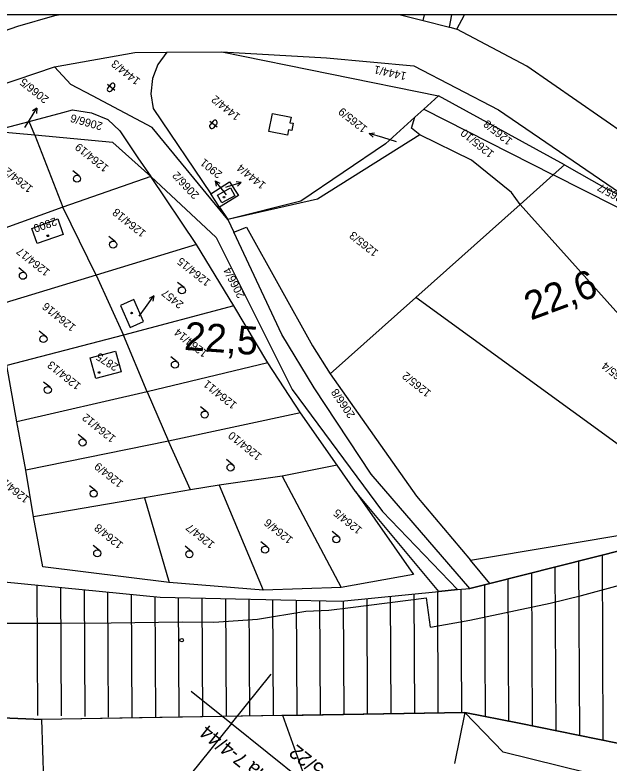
# Model space of a CAD drawing. Extents: x -794765 to -785424, y -1118958 to -1108731.
# Drawn here: x -794200.3 to -794074.2, y -1110190.3 to -1110031.4 of the extents above; entities that cross this region are included whole.
import ezdxf

# ---------------------------------------------------------------- set-up
doc = ezdxf.new("R2010")
doc.units = 0
for name, color, linetype in [('Level 66', 7, 'Continuous'), ('Level 71', 7, 'Continuous'), ('Level 73', 7, 'Continuous'), ('Level 75', 7, 'Continuous'), ('Level 76', 7, 'Continuous'), ('Level 77', 7, 'Continuous'), ('Level 78', 7, 'Continuous'), ('Level 79', 7, 'Continuous'), ('Level 80', 7, 'Continuous'), ('Vrstva 1', 7, 'Continuous'), ('Vrstva 53', 7, 'Continuous')]:
    doc.layers.add(name, color=color, linetype=linetype)

msp = doc.modelspace()

# ---------------------------------------------------------------- linework, layer by layer
at = {"layer": 'Level 66'}
for p, q in [((-794179.12, -1110047.46), (-794180.69, -1110046.2)), ((-794179.98, -1110046.12), (-794180.61, -1110046.91)), ((-794179.83, -1110047.53), (-794179.2, -1110046.75)), ((-794157.42, -1110055.31), (-794158.98, -1110054.06)), ((-794158.27, -1110053.98), (-794158.9, -1110054.76)), ((-794158.12, -1110055.39), (-794157.49, -1110054.61)), ((-794186.69, -1110065.64), (-794188.06, -1110064.55)), ((-794179.01, -1110079.63), (-794180.38, -1110078.53)), ((-794198.17, -1110086.26), (-794199.54, -1110085.17)), ((-794164.42, -1110089.36), (-794165.79, -1110088.27)), ((-794193.8, -1110099.71), (-794195.17, -1110098.61)), ((-794165.9, -1110105.14), (-794167.26, -1110104.04)), ((-794192.88, -1110110.51), (-794194.24, -1110109.42)), ((-794159.57, -1110115.75), (-794160.94, -1110114.65)), ((-794185.51, -1110121.67), (-794186.88, -1110120.58)), ((-794154.09, -1110126.99), (-794155.45, -1110125.89)), ((-794183.15, -1110132.54), (-794184.51, -1110131.44)), ((-794131.62, -1110142.24), (-794132.98, -1110141.14)), ((-794146.75, -1110144.45), (-794148.11, -1110143.35)), ((-794182.39, -1110145.21), (-794183.75, -1110144.12)), ((-794162.83, -1110145.41), (-794164.2, -1110144.31))]:
    msp.add_line(p, q, dxfattribs=at)
for centre in [(-794187.16, -1110066.23), (-794179.48, -1110080.21), (-794198.64, -1110086.85), (-794164.89, -1110089.95), (-794194.27, -1110100.29), (-794166.37, -1110105.72), (-794193.35, -1110111.1), (-794160.04, -1110116.33), (-794185.98, -1110122.26), (-794154.56, -1110127.57), (-794183.62, -1110133.12), (-794132.09, -1110142.82), (-794182.86, -1110145.8), (-794163.3, -1110145.99), (-794147.22, -1110145.03)]:
    msp.add_circle(centre, 0.75, dxfattribs=at)
for centre, start, end in [((-794179.59, -1110046.44), 321.279, 141.2669), ((-794180.22, -1110047.22), 141.279, 321.279), ((-794158.51, -1110055.07), 141.279, 321.279), ((-794157.88, -1110054.29), 321.279, 141.2669)]:
    msp.add_arc(centre, 0.5, start, end, dxfattribs=at)
at = {"layer": 'Level 71'}
msp.add_lwpolyline([(-793908.08, -1110031.45), (-794753.93, -1110031.45), (-794753.93, -1110332.22), (-793908.08, -1110332.22)], dxfattribs=at)
at = {"layer": 'Level 75'}
for p, q in [((-794106.52, -1110034.45), (-794104.92, -1110031.45)), ((-794108.04, -1110034.02), (-794107.69, -1110034.1)), ((-794107.69, -1110034.1), (-794106.52, -1110034.45)), ((-794091.69, -1110042.34), (-794106.52, -1110034.45)), ((-794191.91, -1110042.47), (-794174.87, -1110039.43)), ((-794174.87, -1110039.43), (-794168.06, -1110039.38)), ((-794168.06, -1110039.38), (-794156.44, -1110039.29)), ((-794156.44, -1110039.29), (-794110.41, -1110048.62)), ((-794212.78, -1110049.48), (-794191.91, -1110042.47)), ((-794028.04, -1110086.43), (-794091.69, -1110042.34)), ((-794110.41, -1110048.62), (-794113.55, -1110051.47)), ((-794083.67, -1110063.3), (-794110.41, -1110048.62)), ((-794113.55, -1110051.47), (-794115.45, -1110053.18)), ((-794113.55, -1110051.47), (-794086.03, -1110065.42)), ((-794097.7, -1110051.61), (-794069.06, -1110071.16)), ((-794205.18, -1110056.17), (-794197.29, -1110054.06)), ((-794196.14, -1110057), (-794197.29, -1110054.06)), ((-794196.14, -1110057), (-794205.18, -1110056.17)), ((-794196.14, -1110057), (-794190.13, -1110072.26)), ((-794086.03, -1110065.42), (-794083.67, -1110063.3)), ((-794171.51, -1110065.77), (-794190.13, -1110072.26)), ((-794161.77, -1110080.2), (-794171.51, -1110065.77)), ((-794093.09, -1110071.73), (-794086.03, -1110065.42)), ((-794156.87, -1110072.29), (-794158.77, -1110069.45)), ((-794190.13, -1110072.26), (-794207.61, -1110078.55)), ((-794183.1, -1110086.74), (-794190.13, -1110072.26)), ((-794156.87, -1110072.29), (-794155.11, -1110074.89)), ((-794115.2, -1110091.49), (-794093.09, -1110071.73)), ((-794155.11, -1110074.89), (-794153.84, -1110077.58)), ((-794161.77, -1110080.2), (-794183.1, -1110086.74)), ((-794153.84, -1110093.26), (-794161.77, -1110080.2)), ((-794183.1, -1110086.74), (-794204.4, -1110093.2)), ((-794183.1, -1110086.74), (-794177.29, -1110099.49)), ((-794115.2, -1110091.49), (-794133.43, -1110107.64)), ((-794057.76, -1110133.26), (-794115.2, -1110091.49)), ((-794153.84, -1110093.26), (-794177.29, -1110099.49)), ((-794146.67, -1110105.32), (-794153.84, -1110093.26)), ((-794177.29, -1110099.49), (-794202.07, -1110105.92)), ((-794172.27, -1110111.49), (-794177.29, -1110099.49)), ((-794146.67, -1110105.32), (-794172.27, -1110111.49)), ((-794139.69, -1110115.99), (-794146.67, -1110105.32)), ((-794199.92, -1110117.87), (-794202.07, -1110105.92)), ((-794172.27, -1110111.49), (-794199.92, -1110117.87)), ((-794172.27, -1110111.49), (-794167.73, -1110121.95)), ((-794139.69, -1110115.99), (-794167.73, -1110121.95)), ((-794131.94, -1110127.07), (-794139.69, -1110115.99)), ((-794197.99, -1110128.12), (-794199.92, -1110117.87)), ((-794167.73, -1110121.95), (-794197.99, -1110128.12)), ((-794163.06, -1110132.33), (-794167.73, -1110121.95)), ((-794131.94, -1110127.07), (-794143.61, -1110129.38)), ((-794128.02, -1110132.69), (-794131.94, -1110127.07)), ((-794196.37, -1110138.03), (-794197.99, -1110128.12)), ((-794143.61, -1110129.38), (-794156.99, -1110131.32)), ((-794143.61, -1110129.38), (-794131.04, -1110153.04)), ((-794163.06, -1110132.33), (-794172.83, -1110134.02)), ((-794156.99, -1110131.32), (-794163.06, -1110132.33)), ((-794156.99, -1110131.32), (-794147.62, -1110153.63)), ((-794172.83, -1110134.02), (-794196.37, -1110138.03)), ((-794172.83, -1110134.02), (-794167.57, -1110151.97)), ((-794110.33, -1110153.9), (-794128.02, -1110132.69)), ((-794099.49, -1110152.18), (-794103.65, -1110147.24)), ((-794147.62, -1110153.63), (-794167.57, -1110151.97)), ((-794131.04, -1110153.04), (-794147.62, -1110153.63)), ((-794106.35, -1110153.51), (-794103.73, -1110153.25)), ((-794099.49, -1110152.18), (-794103.73, -1110153.25)), ((-794106.35, -1110153.51), (-794110.33, -1110153.9)), ((-794143.48, -1110180.27), (-794194.62, -1110181.11)), ((-794143.48, -1110180.27), (-794104.85, -1110179.63)), ((-794134.91, -1110204.09), (-794143.48, -1110180.27)), ((-794104.85, -1110179.63), (-794107.01, -1110190.42)), ((-794193.28, -1110225.61), (-794194.62, -1110181.11))]:
    msp.add_line(p, q, dxfattribs=at)
for points in [[(-794199.72, -1110033.84), (-794191.89, -1110031.57), (-794191.05, -1110031.45)], [(-794118.45, -1110031.45), (-794113.66, -1110032.64), (-794108.04, -1110034.02)], [(-794108.04, -1110034.02), (-794107.6, -1110031.45)], [(-794259.1, -1110055.12), (-794254.69, -1110051), (-794229.93, -1110044.38), (-794199.72, -1110033.84)], [(-794168.06, -1110039.38), (-794169.97, -1110041.99), (-794171.1, -1110044.97), (-794171.45, -1110048.18), (-794170.99, -1110051.34), (-794158.77, -1110069.45)], [(-794156.44, -1110039.29), (-794134.18, -1110040.53), (-794115.67, -1110042.26), (-794097.7, -1110051.61)], [(-794155.11, -1110074.89), (-794171.17, -1110055.33), (-794183.86, -1110048.66), (-794188.45, -1110046.25), (-794191.91, -1110042.47)], [(-794197.29, -1110054.06), (-794190.13, -1110052.13), (-794188.12, -1110051.59), (-794184.08, -1110052.24), (-794180.63, -1110053.67), (-794178.06, -1110056.05), (-794174.22, -1110061.76), (-794171.51, -1110065.77)], [(-794115.45, -1110053.18), (-794121.68, -1110058.82), (-794139.67, -1110071), (-794155.11, -1110074.89)], [(-794114.36, -1110056.88), (-794116.17, -1110055.49), (-794115.45, -1110053.18)], [(-794171.51, -1110065.77), (-794179.57, -1110058.52), (-794196.14, -1110057)], [(-794114.36, -1110056.88), (-794136.09, -1110070.55), (-794155.11, -1110074.89)], [(-794093.09, -1110071.73), (-794094.9, -1110069.13), (-794103.38, -1110062.28), (-794114.36, -1110056.88)], [(-794083.67, -1110063.3), (-794074.83, -1110068.31), (-794069.06, -1110071.16)], [(-794171.51, -1110065.77), (-794157.59, -1110078.69), (-794141.51, -1110110.98), (-794122.3, -1110136.9), (-794106.35, -1110153.51)], [(-794031.43, -1110096.1), (-794059.76, -1110078.74), (-794086.03, -1110065.42)], [(-794158.77, -1110069.45), (-794154.78, -1110066.89), (-794152.89, -1110069.78), (-794156.87, -1110072.29)], [(-794157.33, -1110069.73), (-794154.6, -1110068.16), (-794153.66, -1110069.84), (-794156.39, -1110071.35), (-794157.33, -1110069.73)], [(-794044.09, -1110122.17), (-794064.11, -1110103.96), (-794093.09, -1110071.73)], [(-794191.23, -1110074.78), (-794190.11, -1110078.05), (-794195.62, -1110079.96), (-794196.75, -1110076.78), (-794191.23, -1110074.78)], [(-794153.84, -1110077.58), (-794151.18, -1110076.53), (-794137.18, -1110101.76), (-794133.43, -1110107.64)], [(-794103.73, -1110153.25), (-794124.69, -1110129.01), (-794136.79, -1110110.62), (-794143.66, -1110099.3), (-794153.84, -1110077.58)], [(-794177.93, -1110093.14), (-794175.89, -1110097.82), (-794173.06, -1110096.59), (-794175.06, -1110091.9), (-794177.93, -1110093.14)], [(-794178.96, -1110102.83), (-794177.79, -1110107.22), (-794183.17, -1110108.69), (-794184.34, -1110104.27), (-794178.96, -1110102.83)], [(-794133.43, -1110107.64), (-794115.08, -1110133.68), (-794103.65, -1110147.24)], [(-794033.45, -1110131.84), (-794050.15, -1110138.11), (-794063.34, -1110143.06), (-794099.49, -1110152.18)], [(-794128.02, -1110132.69), (-794115.72, -1110150.32), (-794131.04, -1110153.04)], [(-794103.65, -1110147.24), (-794067.64, -1110141.26), (-794057.76, -1110133.26)], [(-794167.57, -1110151.97), (-794194.4, -1110148.65), (-794196.37, -1110138.03)], [(-794202.6, -1110151.84), (-794169.52, -1110155.08), (-794131.09, -1110155.94), (-794110.33, -1110153.9)], [(-794247.72, -1110177.42), (-794245.53, -1110178.97), (-794194.62, -1110181.11)], [(-794104.85, -1110179.63), (-794093.27, -1110181.91), (-794068.2, -1110186.99), (-794062.33, -1110188.18), (-794053.47, -1110200.43), (-794048.23, -1110215.36)], [(-794045.55, -1110254.86), (-794047.92, -1110247.46), (-794054.56, -1110213.48), (-794063.23, -1110199.19), (-794072.9, -1110193.93), (-794096.71, -1110188.04), (-794104.85, -1110179.63)]]:
    msp.add_lwpolyline(points, dxfattribs=at)
at = {"layer": 'Level 77'}
for p, q in [((-794113.66, -1110032.64), (-794113.36, -1110031.45)), ((-794146.4, -1110056.23), (-794145.64, -1110052.37)), ((-794145.64, -1110052.37), (-794141.72, -1110053.14)), ((-794141.72, -1110053.14), (-794141.95, -1110054.33)), ((-794141.95, -1110054.33), (-794141.28, -1110054.46)), ((-794141.28, -1110054.46), (-794141.58, -1110055.99)), ((-794142.49, -1110057.01), (-794146.4, -1110056.23)), ((-794142.26, -1110055.85), (-794142.49, -1110057.01)), ((-794141.58, -1110055.99), (-794142.26, -1110055.85))]:
    msp.add_line(p, q, dxfattribs=at)
at = {"layer": 'Level 78'}
for p, q in [((-794075.69, -1110146.17), (-794075.5, -1110185.53)), ((-794080.68, -1110147.43), (-794080.5, -1110184.52)), ((-794090.67, -1110149.95), (-794090.51, -1110182.51)), ((-794085.68, -1110148.69), (-794085.51, -1110183.52)), ((-794095.66, -1110151.21), (-794095.52, -1110181.51)), ((-794195.66, -1110152.52), (-794195.52, -1110180.23)), ((-794190.66, -1110153.01), (-794190.52, -1110180.35)), ((-794100.66, -1110152.47), (-794100.52, -1110180.5)), ((-794185.65, -1110153.5), (-794185.52, -1110180.48)), ((-794180.65, -1110153.99), (-794180.52, -1110180.6)), ((-794175.65, -1110154.48), (-794175.52, -1110180.73)), ((-794120.65, -1110154.91), (-794120.52, -1110179.89)), ((-794115.65, -1110154.42), (-794115.52, -1110179.81)), ((-794110.65, -1110153.93), (-794110.53, -1110179.72)), ((-794105.65, -1110153.44), (-794105.53, -1110179.64)), ((-794170.65, -1110154.97), (-794170.52, -1110180.71)), ((-794165.65, -1110155.17), (-794165.52, -1110180.63)), ((-794160.64, -1110155.28), (-794160.52, -1110180.55)), ((-794155.64, -1110155.39), (-794155.52, -1110180.47)), ((-794150.64, -1110155.5), (-794150.52, -1110180.38)), ((-794145.64, -1110155.61), (-794145.52, -1110180.3)), ((-794140.64, -1110155.73), (-794140.52, -1110180.22)), ((-794135.64, -1110155.84), (-794135.52, -1110180.14)), ((-794130.64, -1110155.9), (-794130.52, -1110180.05)), ((-794125.64, -1110155.4), (-794125.52, -1110179.97))]:
    msp.add_line(p, q, dxfattribs=at)
at = {"layer": 'Level 79'}
for centre in [(-794155.94, -1110070.15), (-794193.36, -1110078.36), (-794175.56, -1110094.77), (-794182.46, -1110107.39)]:
    msp.add_circle(centre, 0.175, dxfattribs=at)
at = {"layer": 'Level 80'}
for p, q in [((-794197.25, -1110053.8), (-794195.67, -1110051.25)), ((-794195.67, -1110051.25), (-794196.62, -1110051.84)), ((-794195.67, -1110051.25), (-794195.77, -1110052.37)), ((-794198.21, -1110055.37), (-794197.25, -1110053.8)), ((-794125.13, -1110056.65), (-794124.03, -1110056.45)), ((-794122.25, -1110057.51), (-794125.13, -1110056.65)), ((-794125.13, -1110056.65), (-794124.31, -1110057.41)), ((-794119.33, -1110058.4), (-794122.25, -1110057.51)), ((-794155.93, -1110069.01), (-794157.83, -1110066.69)), ((-794157.83, -1110066.69), (-794156.81, -1110067.15)), ((-794157.83, -1110066.69), (-794157.59, -1110067.78)), ((-794155.17, -1110067.9), (-794152.28, -1110067.05)), ((-794152.28, -1110067.05), (-794153.39, -1110066.86)), ((-794152.28, -1110067.05), (-794153.11, -1110067.82)), ((-794155.41, -1110069.64), (-794155.93, -1110069.01)), ((-794155.54, -1110068), (-794155.17, -1110067.9)), ((-794172.61, -1110093.55), (-794170.86, -1110091.12)), ((-794170.86, -1110091.12), (-794171.85, -1110091.64)), ((-794170.86, -1110091.12), (-794171.04, -1110092.22)), ((-794173.97, -1110095.42), (-794172.61, -1110093.55))]:
    msp.add_line(p, q, dxfattribs=at)
at = {"layer": 'Vrstva 1'}
for p, q in [((-794112.11, -1110161.52), (-794112.99, -1110155.22)), ((-794203.12, -1110160.63), (-794196.95, -1110160.62)), ((-794154.35, -1110181.93), (-794145.96, -1110171.47)), ((-794162.9, -1110175.08), (-794154.35, -1110181.93)), ((-794154.35, -1110181.93), (-794163.1, -1110192.85)), ((-794154.35, -1110181.93), (-794108.4, -1110218.77))]:
    msp.add_line(p, q, dxfattribs=at)
for points in [[(-794112.11, -1110161.52), (-794103.74, -1110159.99), (-794086.68, -1110156.38), (-794080.07, -1110154.76), (-794065.46, -1110150.77), (-794056.08, -1110147.87), (-794032.49, -1110139.42), (-794009.33, -1110129.52), (-794000.19, -1110125.13), (-793994.81, -1110122.42), (-793986.14, -1110117.84), (-793985.74, -1110117.63), (-793981.36, -1110115.2), (-793976.26, -1110112.26), (-793967.5, -1110107), (-793959.76, -1110102.11), (-793939.02, -1110087.69), (-793919.34, -1110072.08), (-793908.08, -1110061.95)], [(-794179.9, -1110160.6), (-794164.82, -1110160.33), (-794158.09, -1110160.39), (-794148.81, -1110159.81), (-794138.58, -1110158.1), (-794133.71, -1110157.87), (-794129.1, -1110157.33), (-794112.99, -1110155.22)], [(-794224.58, -1110159.08), (-794220.4, -1110159.38), (-794203.12, -1110160.63), (-794190.71, -1110160.63), (-794179.9, -1110160.6)]]:
    msp.add_lwpolyline(points, dxfattribs=at)
msp.add_circle((-794164.92, -1110164.26), 0.375, dxfattribs=at)
at = {"layer": 'Vrstva 53'}
msp.add_lwpolyline([(-794068.2, -1110186.99), (-794093.27, -1110181.91), (-794104.85, -1110179.63), (-794173.91, -1110180.77), (-794194.62, -1110181.11), (-794245.53, -1110178.97), (-794247.72, -1110177.42), (-794248.21, -1110169.14), (-794248.26, -1110168.33), (-794248.79, -1110168.36), (-794248.25, -1110159.19), (-794247.7, -1110159.29), (-794247.55, -1110158.45), (-794246.09, -1110150.27), (-794244.99, -1110148.9), (-794244.09, -1110147.78), (-794202.6, -1110151.84), (-794169.52, -1110155.08), (-794131.09, -1110155.94), (-794110.33, -1110153.9), (-794106.35, -1110153.51), (-794103.73, -1110153.25), (-794099.49, -1110152.18), (-794063.34, -1110143.06)], dxfattribs=at)

# ---------------------------------------------------------------- texts
at = {"layer": 'Level 73'}
for s, rotation, p in [('22,6', 20.2743, (-794090.82, -1110096.37)), ('22,5', 355.8818, (-794164.51, -1110102.58))]:
    msp.add_text(s, height=6, rotation=rotation, dxfattribs=at).set_placement(p)
at = {"layer": 'Level 76'}
for s, rotation, p in [('1444/3', 141.279, (-794173.58, -1110045.18)), ('1444/1', 167.279, (-794117.09, -1110043.69)), ('2066/5', 141.279, (-794192.99, -1110049.08)), ('1444/2', 141.279, (-794152.32, -1110052.75)), ('1265/9', 141.279, (-794125.37, -1110055.34)), ('2066/6', 164.279, (-794181.57, -1110054.36)), ('1265/8', 141.279, (-794094.57, -1110057.96)), ('1265/10', 141.279, (-794098.44, -1110060.66)), ('1264/19', 141.279, (-794180.29, -1110063.67)), ('2901', 141.279, (-794156.18, -1110065)), ('1264/20', 141.279, (-794196.36, -1110068.06)), ('1444/4', 141.279, (-794146.92, -1110067.32)), ('2066/2', 133.279, (-794161.08, -1110069.6)), ('1265/7', 151.279, (-794069.97, -1110070.48)), ('1264/18', 141.279, (-794172.35, -1110077.53)), ('2800', 199.279, (-794191.79, -1110074.43)), ('1265/3', 141.279, (-794123.04, -1110081.64)), ('1264/17', 141.279, (-794192.74, -1110085.8)), ('1264/15', 141.279, (-794158.62, -1110087.95)), ('2066/4', 117.279, (-794151.46, -1110091.07)), ('2457', 141.279, (-794164.38, -1110092.68)), ('1264/16', 141.279, (-794187.25, -1110097.53)), ('1264/14', 141.279, (-794159.24, -1110103.04)), ('2875', 147.279, (-794178.17, -1110105.81)), ('1264/13', 141.279, (-794186.16, -1110109.96)), ('1265/4', 141.279, (-794069.46, -1110109.37)), ('1265/2', 141.279, (-794111.83, -1110111.47)), ('1264/11', 141.279, (-794153.06, -1110114.02)), ('2066/8', 124.279, (-794128.03, -1110116.38)), ('1264/12', 141.279, (-794178.77, -1110121.12)), ('1264/10', 141.279, (-794147.79, -1110124.93)), ('1264/9', 141.279, (-794177.18, -1110130.7)), ('1264/2', 141.279, (-794197.09, -1110134)), ('1264/5', 141.279, (-794126.45, -1110140.58)), ('1264/6', 141.279, (-794141.14, -1110142.65)), ('1264/8', 141.279, (-794177.2, -1110143.73)), ('1264/7', 141.279, (-794157.76, -1110143.67))]:
    msp.add_text(s, height=1.7, rotation=rotation, dxfattribs=at).set_placement(p)
at = {"layer": 'Vrstva 1'}
for s, p in [('Blatná 7-4/44', (-794140.88, -1110196.95)), ('Blatná 7-5/22', (-794121.93, -1110201.17))]:
    msp.add_text(s, height=3, rotation=141.279, dxfattribs=at).set_placement(p)

doc.saveas('drawing.dxf')
